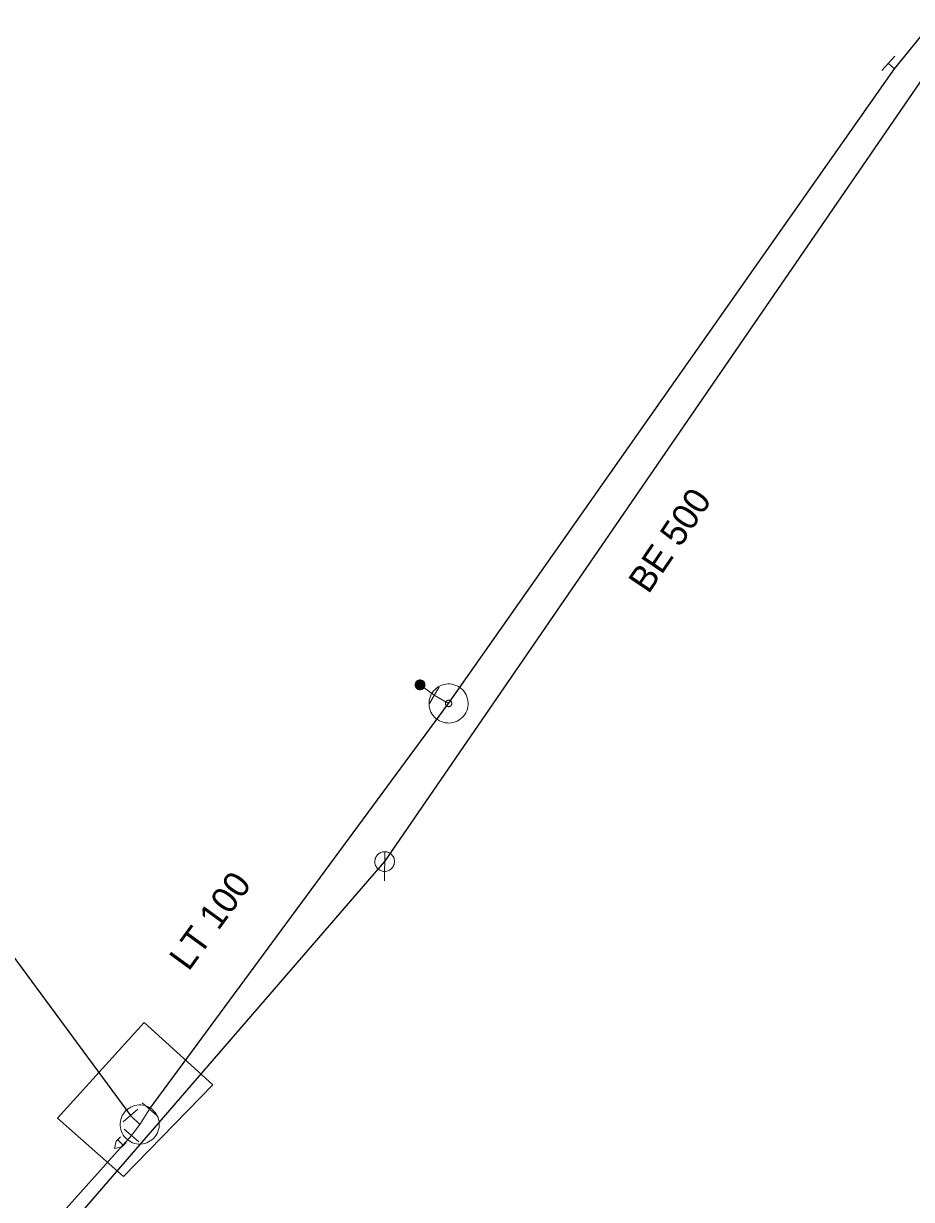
# Model space of a CAD drawing. Extents: x -687515 to -686506, y -974029 to -973461.
# Drawn here: x -687085.95 to -687063.26, y -973866.2 to -973836.14 of the extents above; entities that cross this region are included whole.
import ezdxf
from ezdxf.enums import TextEntityAlignment as Align

# ---------------------------------------------------------------- set-up
doc = ezdxf.new("R2010")
doc.units = 0
doc.header["$LTSCALE"] = 0.27
for name, color, linetype, lineweight in [('1', 7, 'Continuous', 13), ('14', 7, 'Continuous', 25), ('17', 7, 'Continuous', 25), ('2', 7, 'Continuous', 13), ('22', 7, 'Continuous', 13), ('23', 7, 'Continuous', 13), ('34', 7, 'Continuous', 13), ('47', 7, 'Continuous', 13), ('9', 7, 'Continuous', 13)]:
    doc.layers.add(name, color=color, linetype=linetype, lineweight=lineweight)

msp = doc.modelspace()

# ---------------------------------------------------------------- linework, layer by layer
at = {"layer": '14'}
for p, q in [((-687062.584, -973836.971), (-687076.719, -973857.559)), ((-687076.719, -973857.559), (-687098.575, -973882.82))]:
    msp.add_line(p, q, dxfattribs=at)
at = {"layer": '14', "lineweight": 13}
for p, q in [((-687063.695, -973837.3), (-687063.849, -973837.159)), ((-687082.727, -973863.89), (-687082.977, -973864.279)), ((-687082.977, -973864.279), (-687083.209, -973864.046)), ((-687082.977, -973864.279), (-687083.189, -973864.557))]:
    msp.add_line(p, q, dxfattribs=at)
msp.add_lwpolyline([(-687075.086, -973853.519), (-687075.451, -973853.306), (-687075.815, -973853.042)], dxfattribs=at)
at = {"layer": '17'}
msp.add_line((-687082.727, -973863.89), (-687075.086, -973853.519), dxfattribs=at)
for points in [[(-687075.086, -973853.519), (-687063.695, -973837.3), (-687051.693, -973822.548), (-687047.027, -973818.188), (-687028.776, -973805.013), (-687019.272, -973801.323), (-687004.054, -973797.199), (-686987.892, -973793.361), (-686982.074, -973791.647), (-686976.761, -973790.276)], [(-687106.566, -973836.941), (-687102.715, -973840.21), (-687096.25, -973846.366), (-687083.209, -973864.046)], [(-687105.661, -973883.258), (-687101.135, -973882.127), (-687093.84, -973876.458), (-687083.189, -973864.557)]]:
    msp.add_lwpolyline(points, dxfattribs=at)
at = {"layer": '2'}
msp.add_lwpolyline([(-687083.389, -973865.609), (-687081.107, -973863.261), (-687082.86, -973861.674), (-687085.076, -973864.121)], close=True, dxfattribs=at)
at = {"layer": '22'}
msp.add_line((-687076.718, -973857.307), (-687076.719, -973858.051), dxfattribs=at)
msp.add_lwpolyline([(-687076.467, -973857.559), (-687076.468, -973857.533), (-687076.472, -973857.507), (-687076.478, -973857.481), (-687076.488, -973857.457), (-687076.5, -973857.433), (-687076.514, -973857.411), (-687076.531, -973857.39), (-687076.549, -973857.372), (-687076.57, -973857.355), (-687076.592, -973857.341), (-687076.616, -973857.329), (-687076.64, -973857.319), (-687076.666, -973857.313), (-687076.692, -973857.309), (-687076.718, -973857.307), (-687076.744, -973857.308), (-687076.77, -973857.312), (-687076.796, -973857.318), (-687076.821, -973857.328), (-687076.844, -973857.34), (-687076.866, -973857.354), (-687076.887, -973857.371), (-687076.905, -973857.389), (-687076.922, -973857.41), (-687076.936, -973857.432), (-687076.948, -973857.456), (-687076.958, -973857.48), (-687076.965, -973857.506), (-687076.969, -973857.532), (-687076.971, -973857.558), (-687076.97, -973857.584), (-687076.966, -973857.61), (-687076.959, -973857.636), (-687076.949, -973857.661), (-687076.937, -973857.684), (-687076.923, -973857.706), (-687076.906, -973857.727), (-687076.888, -973857.745), (-687076.867, -973857.762), (-687076.845, -973857.776), (-687076.822, -973857.788), (-687076.797, -973857.798), (-687076.771, -973857.805), (-687076.745, -973857.809), (-687076.719, -973857.811), (-687076.693, -973857.81), (-687076.667, -973857.806), (-687076.641, -973857.799), (-687076.617, -973857.789), (-687076.593, -973857.777), (-687076.571, -973857.763), (-687076.55, -973857.746), (-687076.532, -973857.728), (-687076.515, -973857.707), (-687076.501, -973857.685), (-687076.489, -973857.662), (-687076.479, -973857.637), (-687076.473, -973857.611), (-687076.469, -973857.585)], close=True, dxfattribs=at)
at = {"layer": '23'}
msp.add_line((-687083.54, -973864.666), (-687083.395, -973864.812), dxfattribs=at)
msp.add_lwpolyline([(-687083.329, -973863.924), (-687083.364, -973863.963), (-687083.395, -973864.005), (-687083.421, -973864.05), (-687083.443, -973864.097), (-687083.459, -973864.148), (-687083.47, -973864.199), (-687083.475, -973864.251), (-687083.475, -973864.303), (-687083.47, -973864.355), (-687083.46, -973864.406), (-687083.444, -973864.457), (-687083.422, -973864.504), (-687083.397, -973864.549), (-687083.366, -973864.592), (-687083.331, -973864.631), (-687083.292, -973864.666), (-687083.25, -973864.697), (-687083.204, -973864.723), (-687083.158, -973864.745), (-687083.107, -973864.761), (-687083.056, -973864.772), (-687083.004, -973864.778), (-687082.951, -973864.778), (-687082.9, -973864.773), (-687082.849, -973864.762), (-687082.798, -973864.746), (-687082.75, -973864.725), (-687082.706, -973864.699), (-687082.663, -973864.668), (-687082.624, -973864.633), (-687082.589, -973864.594), (-687082.558, -973864.552), (-687082.531, -973864.507), (-687082.51, -973864.46), (-687082.494, -973864.409), (-687082.482, -973864.359), (-687082.477, -973864.306), (-687082.476, -973864.254), (-687082.482, -973864.202), (-687082.493, -973864.151), (-687082.509, -973864.1), (-687082.53, -973864.053), (-687082.556, -973864.008), (-687082.587, -973863.965), (-687082.622, -973863.926), (-687082.661, -973863.891), (-687082.703, -973863.86), (-687082.747, -973863.834), (-687082.795, -973863.812), (-687082.846, -973863.796), (-687082.896, -973863.784), (-687082.948, -973863.779), (-687083, -973863.779), (-687083.053, -973863.785), (-687083.104, -973863.795), (-687083.155, -973863.811), (-687083.201, -973863.832), (-687083.247, -973863.858), (-687083.29, -973863.889)], close=True, dxfattribs=at)
msp.add_lwpolyline([(-687083.329, -973863.924), (-687083.364, -973863.963), (-687083.395, -973864.005), (-687083.421, -973864.05), (-687083.443, -973864.097), (-687083.459, -973864.148), (-687083.47, -973864.199), (-687083.475, -973864.251), (-687083.475, -973864.303), (-687083.47, -973864.355), (-687083.46, -973864.406), (-687083.444, -973864.457), (-687083.422, -973864.504), (-687083.397, -973864.549), (-687083.366, -973864.592), (-687083.331, -973864.631), (-687083.292, -973864.666), (-687083.25, -973864.697), (-687083.204, -973864.723), (-687083.158, -973864.745), (-687083.107, -973864.761), (-687083.056, -973864.772), (-687083.004, -973864.778), (-687082.951, -973864.778), (-687082.9, -973864.773), (-687082.849, -973864.762), (-687082.798, -973864.746), (-687082.75, -973864.725), (-687082.706, -973864.699), (-687082.663, -973864.668), (-687082.624, -973864.633), (-687082.589, -973864.594), (-687082.558, -973864.552), (-687082.531, -973864.507), (-687082.51, -973864.46), (-687082.494, -973864.409), (-687082.482, -973864.359), (-687082.477, -973864.306), (-687082.476, -973864.254), (-687082.482, -973864.202), (-687082.493, -973864.151), (-687082.509, -973864.1), (-687082.53, -973864.053), (-687082.556, -973864.008), (-687082.587, -973863.965), (-687082.622, -973863.926), (-687082.661, -973863.891), (-687082.703, -973863.86), (-687082.747, -973863.834), (-687082.795, -973863.812), (-687082.846, -973863.796), (-687082.896, -973863.784), (-687082.948, -973863.779), (-687083, -973863.779), (-687083.053, -973863.785), (-687083.104, -973863.795), (-687083.155, -973863.811), (-687083.201, -973863.832), (-687083.247, -973863.858), (-687083.29, -973863.889)], close=True, dxfattribs=at)
msp.add_lwpolyline([(-687083.323, -973864.74), (-687083.434, -973864.85), (-687083.619, -973864.889), (-687083.579, -973864.705), (-687083.468, -973864.594)], dxfattribs=at)
at = {"layer": '34'}
for p, q in [((-687064.016, -973837.341), (-687063.681, -973836.976)), ((-687075.326, -973853.091), (-687075.575, -973853.52)), ((-687083.396, -973864.207), (-687083.021, -973863.884)), ((-687082.539, -973864.052), (-687082.914, -973863.727)), ((-687083.001, -973864.719), (-687083.376, -973864.394))]:
    msp.add_line(p, q, dxfattribs=at)
at = {"layer": '47'}
for points in [[(-687074.85, -973853.078), (-687074.897, -973853.056), (-687074.947, -973853.038), (-687074.997, -973853.027), (-687075.049, -973853.02), (-687075.102, -973853.019), (-687075.154, -973853.024), (-687075.205, -973853.034), (-687075.255, -973853.049), (-687075.303, -973853.069), (-687075.349, -973853.094), (-687075.393, -973853.124), (-687075.432, -973853.159), (-687075.468, -973853.196), (-687075.499, -973853.238), (-687075.526, -973853.283), (-687075.548, -973853.33), (-687075.566, -973853.38), (-687075.577, -973853.431), (-687075.584, -973853.482), (-687075.585, -973853.535), (-687075.58, -973853.587), (-687075.571, -973853.639), (-687075.555, -973853.689), (-687075.536, -973853.737), (-687075.51, -973853.782), (-687075.48, -973853.826), (-687075.446, -973853.866), (-687075.408, -973853.901), (-687075.366, -973853.932), (-687075.321, -973853.959), (-687075.274, -973853.981), (-687075.224, -973853.999), (-687075.173, -973854.011), (-687075.122, -973854.017), (-687075.069, -973854.018), (-687075.017, -973854.014), (-687074.966, -973854.005), (-687074.916, -973853.989), (-687074.867, -973853.969), (-687074.822, -973853.943), (-687074.778, -973853.913), (-687074.739, -973853.88), (-687074.703, -973853.841), (-687074.672, -973853.799), (-687074.645, -973853.754), (-687074.623, -973853.707), (-687074.605, -973853.657), (-687074.593, -973853.607), (-687074.587, -973853.555), (-687074.586, -973853.502), (-687074.59, -973853.45), (-687074.6, -973853.399), (-687074.615, -973853.349), (-687074.636, -973853.301), (-687074.661, -973853.255), (-687074.691, -973853.211), (-687074.725, -973853.173), (-687074.763, -973853.136), (-687074.805, -973853.105)], [(-687075.047, -973853.446), (-687075.055, -973853.442), (-687075.063, -973853.44), (-687075.071, -973853.438), (-687075.079, -973853.437), (-687075.088, -973853.437), (-687075.097, -973853.438), (-687075.105, -973853.439), (-687075.113, -973853.441), (-687075.121, -973853.445), (-687075.129, -973853.449), (-687075.136, -973853.454), (-687075.142, -973853.46), (-687075.148, -973853.466), (-687075.154, -973853.472), (-687075.158, -973853.48), (-687075.162, -973853.488), (-687075.164, -973853.496), (-687075.166, -973853.504), (-687075.167, -973853.512), (-687075.167, -973853.521), (-687075.166, -973853.53), (-687075.165, -973853.538), (-687075.163, -973853.546), (-687075.159, -973853.555), (-687075.155, -973853.562), (-687075.15, -973853.569), (-687075.144, -973853.575), (-687075.138, -973853.581), (-687075.132, -973853.587), (-687075.124, -973853.591), (-687075.116, -973853.595), (-687075.108, -973853.597), (-687075.1, -973853.599), (-687075.092, -973853.6), (-687075.083, -973853.6), (-687075.075, -973853.6), (-687075.066, -973853.598), (-687075.058, -973853.596), (-687075.049, -973853.592), (-687075.042, -973853.588), (-687075.035, -973853.583), (-687075.029, -973853.577), (-687075.023, -973853.571), (-687075.017, -973853.565), (-687075.013, -973853.557), (-687075.009, -973853.549), (-687075.007, -973853.541), (-687075.005, -973853.533), (-687075.004, -973853.525), (-687075.004, -973853.516), (-687075.004, -973853.508), (-687075.006, -973853.499), (-687075.008, -973853.491), (-687075.012, -973853.483), (-687075.016, -973853.475), (-687075.021, -973853.468), (-687075.027, -973853.462), (-687075.033, -973853.456), (-687075.039, -973853.45)]]:
    msp.add_lwpolyline(points, close=True, dxfattribs=at)
at = {"layer": '9'}
for points in [[(-687075.688, -973853.042), (-687075.69, -973853.029), (-687075.691, -973853.016), (-687075.695, -973853.003), (-687075.7, -973852.991), (-687075.705, -973852.979), (-687075.713, -973852.968), (-687075.72, -973852.958), (-687075.73, -973852.948), (-687075.74, -973852.94), (-687075.752, -973852.933), (-687075.764, -973852.927), (-687075.776, -973852.922), (-687075.789, -973852.919), (-687075.801, -973852.917), (-687075.815, -973852.916), (-687075.828, -973852.917), (-687075.84, -973852.919), (-687075.853, -973852.922), (-687075.865, -973852.927), (-687075.877, -973852.933), (-687075.889, -973852.94), (-687075.899, -973852.948), (-687075.909, -973852.958), (-687075.916, -973852.968), (-687075.924, -973852.979), (-687075.929, -973852.991), (-687075.934, -973853.003), (-687075.938, -973853.016), (-687075.94, -973853.029), (-687075.941, -973853.042), (-687075.94, -973853.055), (-687075.938, -973853.068), (-687075.934, -973853.081), (-687075.929, -973853.093), (-687075.924, -973853.105), (-687075.916, -973853.116), (-687075.909, -973853.126), (-687075.899, -973853.136), (-687075.889, -973853.144), (-687075.877, -973853.151), (-687075.865, -973853.157), (-687075.853, -973853.162), (-687075.84, -973853.165), (-687075.828, -973853.167), (-687075.815, -973853.168), (-687075.801, -973853.167), (-687075.789, -973853.165), (-687075.776, -973853.162), (-687075.764, -973853.157), (-687075.752, -973853.151), (-687075.74, -973853.144), (-687075.73, -973853.136), (-687075.72, -973853.126), (-687075.713, -973853.116), (-687075.705, -973853.105), (-687075.7, -973853.093), (-687075.695, -973853.081), (-687075.691, -973853.068), (-687075.69, -973853.055)], [(-687075.708, -973853.042), (-687075.708, -973853.031), (-687075.71, -973853.02), (-687075.713, -973853.009), (-687075.718, -973852.999), (-687075.723, -973852.989), (-687075.728, -973852.98), (-687075.735, -973852.971), (-687075.744, -973852.963), (-687075.752, -973852.956), (-687075.762, -973852.95), (-687075.772, -973852.945), (-687075.781, -973852.941), (-687075.793, -973852.938), (-687075.803, -973852.936), (-687075.815, -973852.936), (-687075.826, -973852.936), (-687075.837, -973852.938), (-687075.848, -973852.941), (-687075.857, -973852.945), (-687075.867, -973852.95), (-687075.877, -973852.956), (-687075.886, -973852.963), (-687075.894, -973852.971), (-687075.901, -973852.98), (-687075.906, -973852.989), (-687075.911, -973852.999), (-687075.916, -973853.009), (-687075.919, -973853.02), (-687075.921, -973853.031), (-687075.921, -973853.042), (-687075.921, -973853.053), (-687075.919, -973853.064), (-687075.916, -973853.075), (-687075.911, -973853.085), (-687075.906, -973853.095), (-687075.901, -973853.104), (-687075.894, -973853.113), (-687075.886, -973853.121), (-687075.877, -973853.128), (-687075.867, -973853.134), (-687075.857, -973853.139), (-687075.848, -973853.143), (-687075.837, -973853.146), (-687075.826, -973853.148), (-687075.815, -973853.148), (-687075.803, -973853.148), (-687075.793, -973853.146), (-687075.781, -973853.143), (-687075.772, -973853.139), (-687075.762, -973853.134), (-687075.752, -973853.128), (-687075.744, -973853.121), (-687075.735, -973853.113), (-687075.728, -973853.104), (-687075.723, -973853.095), (-687075.718, -973853.085), (-687075.713, -973853.075), (-687075.71, -973853.064), (-687075.708, -973853.053)], [(-687075.727, -973853.042), (-687075.728, -973853.033), (-687075.73, -973853.024), (-687075.732, -973853.015), (-687075.735, -973853.007), (-687075.74, -973852.999), (-687075.745, -973852.991), (-687075.75, -973852.984), (-687075.757, -973852.978), (-687075.764, -973852.972), (-687075.772, -973852.967), (-687075.779, -973852.963), (-687075.788, -973852.96), (-687075.796, -973852.957), (-687075.806, -973852.956), (-687075.815, -973852.955), (-687075.823, -973852.956), (-687075.833, -973852.957), (-687075.842, -973852.96), (-687075.85, -973852.963), (-687075.857, -973852.967), (-687075.865, -973852.972), (-687075.872, -973852.978), (-687075.879, -973852.984), (-687075.884, -973852.991), (-687075.889, -973852.999), (-687075.894, -973853.007), (-687075.897, -973853.015), (-687075.899, -973853.024), (-687075.901, -973853.033), (-687075.902, -973853.042), (-687075.901, -973853.051), (-687075.899, -973853.06), (-687075.897, -973853.069), (-687075.894, -973853.077), (-687075.889, -973853.085), (-687075.884, -973853.093), (-687075.879, -973853.1), (-687075.872, -973853.106), (-687075.865, -973853.112), (-687075.857, -973853.117), (-687075.85, -973853.121), (-687075.842, -973853.124), (-687075.833, -973853.127), (-687075.823, -973853.128), (-687075.815, -973853.129), (-687075.806, -973853.128), (-687075.796, -973853.127), (-687075.788, -973853.124), (-687075.779, -973853.121), (-687075.772, -973853.117), (-687075.764, -973853.112), (-687075.757, -973853.106), (-687075.75, -973853.1), (-687075.745, -973853.093), (-687075.74, -973853.085), (-687075.735, -973853.077), (-687075.732, -973853.069), (-687075.73, -973853.06), (-687075.728, -973853.051)], [(-687075.747, -973853.042), (-687075.747, -973853.035), (-687075.75, -973853.028), (-687075.75, -973853.021), (-687075.754, -973853.015), (-687075.757, -973853.009), (-687075.761, -973853.003), (-687075.764, -973852.997), (-687075.769, -973852.992), (-687075.776, -973852.988), (-687075.781, -973852.984), (-687075.788, -973852.981), (-687075.794, -973852.978), (-687075.801, -973852.977), (-687075.808, -973852.975), (-687075.815, -973852.975), (-687075.821, -973852.975), (-687075.828, -973852.977), (-687075.835, -973852.978), (-687075.842, -973852.981), (-687075.848, -973852.984), (-687075.853, -973852.988), (-687075.86, -973852.992), (-687075.865, -973852.997), (-687075.869, -973853.003), (-687075.872, -973853.009), (-687075.875, -973853.015), (-687075.879, -973853.021), (-687075.88, -973853.028), (-687075.882, -973853.035), (-687075.882, -973853.042), (-687075.882, -973853.049), (-687075.88, -973853.056), (-687075.879, -973853.063), (-687075.875, -973853.069), (-687075.872, -973853.076), (-687075.869, -973853.081), (-687075.865, -973853.087), (-687075.86, -973853.092), (-687075.853, -973853.096), (-687075.848, -973853.1), (-687075.842, -973853.103), (-687075.835, -973853.106), (-687075.828, -973853.108), (-687075.821, -973853.109), (-687075.815, -973853.109), (-687075.808, -973853.109), (-687075.801, -973853.108), (-687075.794, -973853.106), (-687075.788, -973853.103), (-687075.781, -973853.1), (-687075.776, -973853.096), (-687075.769, -973853.092), (-687075.764, -973853.087), (-687075.761, -973853.081), (-687075.757, -973853.076), (-687075.754, -973853.069), (-687075.75, -973853.063), (-687075.75, -973853.056), (-687075.747, -973853.049)], [(-687075.767, -973853.042), (-687075.767, -973853.037), (-687075.769, -973853.032), (-687075.769, -973853.027), (-687075.772, -973853.023), (-687075.774, -973853.018), (-687075.777, -973853.014), (-687075.779, -973853.011), (-687075.784, -973853.007), (-687075.786, -973853.004), (-687075.791, -973853.001), (-687075.796, -973852.999), (-687075.799, -973852.997), (-687075.804, -973852.996), (-687075.809, -973852.995), (-687075.815, -973852.995), (-687075.82, -973852.995), (-687075.825, -973852.996), (-687075.83, -973852.997), (-687075.833, -973852.999), (-687075.838, -973853.001), (-687075.843, -973853.004), (-687075.847, -973853.007), (-687075.85, -973853.011), (-687075.852, -973853.014), (-687075.855, -973853.018), (-687075.857, -973853.023), (-687075.86, -973853.027), (-687075.86, -973853.032), (-687075.862, -973853.037), (-687075.862, -973853.042), (-687075.862, -973853.047), (-687075.86, -973853.052), (-687075.86, -973853.057), (-687075.857, -973853.061), (-687075.855, -973853.066), (-687075.852, -973853.07), (-687075.85, -973853.074), (-687075.847, -973853.077), (-687075.843, -973853.08), (-687075.838, -973853.083), (-687075.833, -973853.085), (-687075.83, -973853.087), (-687075.825, -973853.088), (-687075.82, -973853.089), (-687075.815, -973853.089), (-687075.809, -973853.089), (-687075.804, -973853.088), (-687075.799, -973853.087), (-687075.796, -973853.085), (-687075.791, -973853.083), (-687075.786, -973853.08), (-687075.784, -973853.077), (-687075.779, -973853.074), (-687075.777, -973853.07), (-687075.774, -973853.066), (-687075.772, -973853.061), (-687075.769, -973853.057), (-687075.769, -973853.052), (-687075.767, -973853.047)], [(-687075.788, -973853.042), (-687075.788, -973853.039), (-687075.788, -973853.036), (-687075.789, -973853.034), (-687075.789, -973853.031), (-687075.791, -973853.028), (-687075.793, -973853.026), (-687075.794, -973853.024), (-687075.796, -973853.022), (-687075.799, -973853.02), (-687075.801, -973853.018), (-687075.803, -973853.017), (-687075.806, -973853.016), (-687075.808, -973853.015), (-687075.811, -973853.015), (-687075.815, -973853.015), (-687075.818, -973853.015), (-687075.821, -973853.015), (-687075.823, -973853.016), (-687075.826, -973853.017), (-687075.828, -973853.018), (-687075.83, -973853.02), (-687075.833, -973853.022), (-687075.835, -973853.024), (-687075.837, -973853.026), (-687075.838, -973853.028), (-687075.84, -973853.031), (-687075.84, -973853.034), (-687075.842, -973853.036), (-687075.842, -973853.039), (-687075.843, -973853.042), (-687075.842, -973853.045), (-687075.842, -973853.048), (-687075.84, -973853.051), (-687075.84, -973853.053), (-687075.838, -973853.056), (-687075.837, -973853.058), (-687075.835, -973853.061), (-687075.833, -973853.063), (-687075.83, -973853.064), (-687075.828, -973853.066), (-687075.826, -973853.067), (-687075.823, -973853.068), (-687075.821, -973853.069), (-687075.818, -973853.069), (-687075.815, -973853.07), (-687075.811, -973853.069), (-687075.808, -973853.069), (-687075.806, -973853.068), (-687075.803, -973853.067), (-687075.801, -973853.066), (-687075.799, -973853.064), (-687075.796, -973853.063), (-687075.794, -973853.061), (-687075.793, -973853.058), (-687075.791, -973853.056), (-687075.789, -973853.053), (-687075.789, -973853.051), (-687075.788, -973853.048), (-687075.788, -973853.045)], [(-687075.806, -973853.042), (-687075.806, -973853.041), (-687075.806, -973853.04), (-687075.808, -973853.04), (-687075.808, -973853.039), (-687075.808, -973853.038), (-687075.808, -973853.037), (-687075.808, -973853.037), (-687075.809, -973853.036), (-687075.809, -973853.036), (-687075.811, -973853.035), (-687075.811, -973853.035), (-687075.813, -973853.035), (-687075.813, -973853.034), (-687075.813, -973853.034), (-687075.815, -973853.034), (-687075.816, -973853.034), (-687075.816, -973853.034), (-687075.816, -973853.035), (-687075.818, -973853.035), (-687075.818, -973853.035), (-687075.82, -973853.036), (-687075.82, -973853.036), (-687075.821, -973853.037), (-687075.821, -973853.037), (-687075.821, -973853.038), (-687075.821, -973853.039), (-687075.823, -973853.04), (-687075.823, -973853.04), (-687075.823, -973853.041), (-687075.823, -973853.042), (-687075.823, -973853.043), (-687075.823, -973853.044), (-687075.823, -973853.044), (-687075.821, -973853.045), (-687075.821, -973853.046), (-687075.821, -973853.047), (-687075.821, -973853.047), (-687075.82, -973853.048), (-687075.82, -973853.048), (-687075.818, -973853.049), (-687075.818, -973853.049), (-687075.816, -973853.05), (-687075.816, -973853.05), (-687075.816, -973853.05), (-687075.815, -973853.05), (-687075.813, -973853.05), (-687075.813, -973853.05), (-687075.813, -973853.05), (-687075.811, -973853.049), (-687075.811, -973853.049), (-687075.809, -973853.048), (-687075.809, -973853.048), (-687075.808, -973853.047), (-687075.808, -973853.047), (-687075.808, -973853.046), (-687075.808, -973853.045), (-687075.808, -973853.044), (-687075.806, -973853.044), (-687075.806, -973853.043)]]:
    msp.add_lwpolyline(points, close=True, dxfattribs=at)

# ---------------------------------------------------------------- texts
at = {"layer": '1'}
for s, rotation, p in [('BE 500', 56, (-687069.16, -973849.53)), ('LT 100', 54, (-687080.911, -973859.261))]:
    msp.add_text(s, height=0.6667, rotation=rotation, dxfattribs=at).set_placement(p, align=Align.CENTER)

doc.saveas('drawing.dxf')
